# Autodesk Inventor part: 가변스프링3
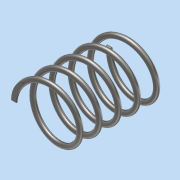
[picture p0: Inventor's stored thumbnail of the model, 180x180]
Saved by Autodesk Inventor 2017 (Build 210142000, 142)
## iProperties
Part Number: 가변스프링3
Material: 강철, 연강
Document SubType Name: Modeling
Designer: MRC
Density: 7.85 g/cm^3
Appearance: 반연마
Mass: 8.42555 g
Surface Area: 21.7274 cm^2
Volume: 1.07332 cm^3
Author: MRC
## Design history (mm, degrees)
sketch "스케치1"
  geometry: L1 (0, 0)-(0, 37.411); L2 (0, 0)-(-11, 0); L3 (0, 37.411)-(-11, 37.411); C1 r 1 at (-11, 0)
  constraints: 6 end point, 2 horizontal, 1 centre point, 1 coincident, 1 vertical
  dimensions: "d0" = 37.4112 distance of L1.start L1.end (derived); "d11" = 11 distance of L1.start L2.end; "d12" = 2 diameter of C1
feature "코일1" sketch "스케치1" pitch "d3" = 10; turns "d5" = 5; dims "d4" = 37.4112 (= d0), "d6" = 0, angle "d7" = 90 deg, angle "d8" = 90 deg, "d9" = 0, "d10" = 0
sketch "스케치2"
  geometry: L1 (37.411, 17.5)-(0, 17.5); L2 (0, 17.5)-(0, -17.5); L3 (0, -17.5)-(37.411, -17.5); L4 (37.411, -17.5)-(37.411, 17.5); 2 further points
  constraints: 8 end point, 2 parallel, 1 coincident, 1 horizontal, 1 midpoint, 1 perpendicular
  dimensions: "d13" = 37.4112 distance of L2.end L3.end (= d0); "d14" = 35 distance of L3.end L1.start
extrude "돌출1" sketch "스케치2" stored distance "d15" = 10; taper "d16" = 0 deg
node "솔리드1"
